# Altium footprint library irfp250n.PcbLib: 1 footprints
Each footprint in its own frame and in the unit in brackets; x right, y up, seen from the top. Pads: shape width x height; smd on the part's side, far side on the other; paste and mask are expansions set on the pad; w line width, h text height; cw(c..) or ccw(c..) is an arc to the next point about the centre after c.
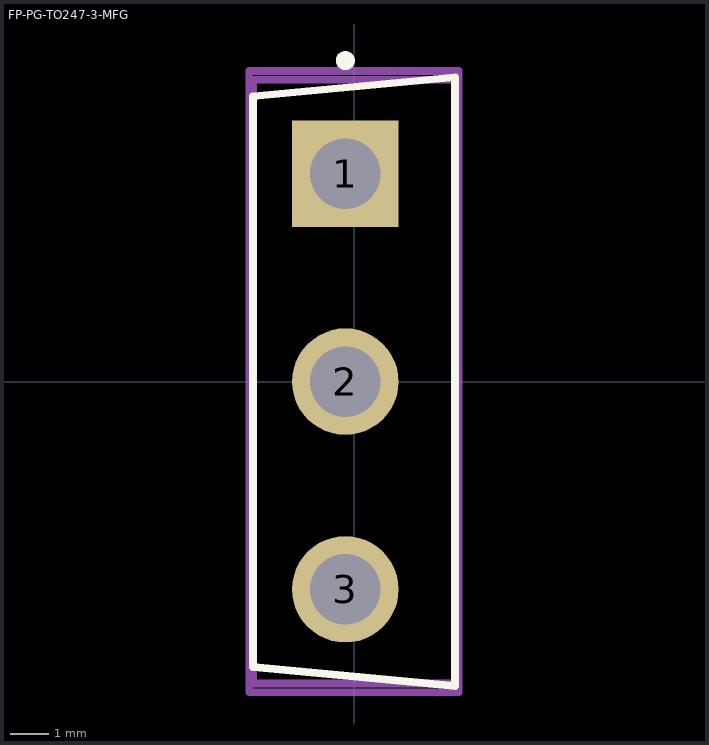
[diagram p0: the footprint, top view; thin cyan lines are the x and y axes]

## FP-PG-TO247-3-MFG [mm]
pads (3):
  rect 2.8x2.8 hole 1.85 paste-1000 mask+0: 1(-0.228,5.46)
  round 2.8 hole 1.85 paste-1000 mask+0: 2(-0.228,0) 3(-0.228,-5.46)
Top Overlay:
  circle w0.25: c-0.228,8.435 r0.125
  lines w0.2: 2.655,-8 -2.655,-7.5 -2.655,7.5 2.655,8 ; 2.655,-7.935 2.655,7.935
Mechanical 5:
  lines w0.2: -2.755,-8.162 2.755,-8.162 2.755,8.162 -2.755,8.162 -2.755,-8.162
  text ".Designator" at 0,-0.001 h1
Mechanical 13:
  lines w0.2: -2.655,-7.935 2.655,-7.935 2.655,7.935 -2.655,7.935 -2.655,-7.935
Mechanical 15:
  lines w0.2: -2.755,-8.162 2.755,-8.162 2.755,8.162 -2.755,8.162 -2.755,-8.162
Mechanical 16:
  lines w0.1: -0.5,0 0.5,0 ; 0,-0.5 0,0.5
3D body "Trans_Infineon_IRFP250NPBF_eec.STEP": height 0.25, standoff 0, extent -2.755,-8.162 2.755,8.162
